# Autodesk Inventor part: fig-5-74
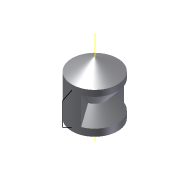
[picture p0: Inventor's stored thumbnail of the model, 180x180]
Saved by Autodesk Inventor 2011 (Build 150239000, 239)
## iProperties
Created: 2004-05
Part Number: fig-5-74
Document SubType Name: Modeling
Designer: CADCIM Technologies
Manufacturer: Standard
Standards Organization: Custom
Density: 1 g/cm^3
Author: CADCIM Technologies
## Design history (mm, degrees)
sketch "Sketch1"
  geometry: L1 (0, -21.51)-(0, 21.51); L2 (0, 21.51)-(-14.639, 13.059); L3 (-14.639, 13.059)-(-14.639, -13.059); L4 (-14.639, -13.059)-(0, -21.51); 2 further points
  constraints: 8 end point, 1 coincident, 1 equal length, 1 midpoint, 1 parallel, 1 vertical, 1 other
  dimensions: "d3" = 120 deg angle of L4 L3
revolve "Revolution1" sketch "Sketch1" stored, may be unused: angle "d0" = 90 deg
workaxis "Work Axis1"
sketch "Sketch2"
  geometry: L1 (-15.658, 10.423)-(-7.144, 0); L2 (-7.144, 0)-(-15.658, -9.738); L3 (-15.658, -9.738)-(-15.658, 10.423); L4 (0, -25.812)-(0, 34.416) reference
  constraints: 6 end point, 1 vertical
revolve "Revolution2" sketch "Sketch2" stored, may be unused: angle "d4" = 140 deg
sketch "Sketch3"
  geometry: L1 (-14.955, 9.983)-(-20.736, 7.191); L2 (-20.736, 7.191)-(-20.736, -7.686); L3 (-20.736, -7.686)-(-15, -10.57); L4 (0, -25.812)-(0, 34.416) reference
  constraints: 6 end point, 1 equal length, 1 vertical
body "Solid1"
